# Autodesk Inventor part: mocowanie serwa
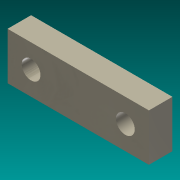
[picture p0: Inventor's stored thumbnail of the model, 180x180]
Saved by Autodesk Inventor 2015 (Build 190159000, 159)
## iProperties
Created: 2016-02
Part Number: mocowanie serwa
Material: Generic
Document SubType Name: Modeling
Designer: Rafał
Density: 1 g/cm^3
Appearance: Light Beige
Author: Rafał
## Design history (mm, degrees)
sketch "Sketch1"
  geometry: L1 (0, 0)-(30, 0); L2 (30, 0)-(30, 10); L3 (30, 10)-(0, 10); L4 (0, 10)-(0, 0); L5 (15, 10)-(15, 0); C1 r 2 at (25, 5); C2 r 2 at (5, 5)
  constraints: 10 end point, 2 centre point, 2 midpoint, 2 parallel, 1 horizontal, 1 perpendicular, 1 symmetric about line, 1 other
  dimensions: "d0" = 30 distance of L3.end L2.end; "d1" = 10 distance of L2.end L1.end; "d2" = 4 diameter of C1; "d3" = 5 distance from line of L2 C1.centre; "d4" = 5 distance from line of C1.centre L1
extrude "Extrusion1" new body sketch "Sketch1" distance "d5" = 5; taper "d6" = 0 deg
body "Solid1"
